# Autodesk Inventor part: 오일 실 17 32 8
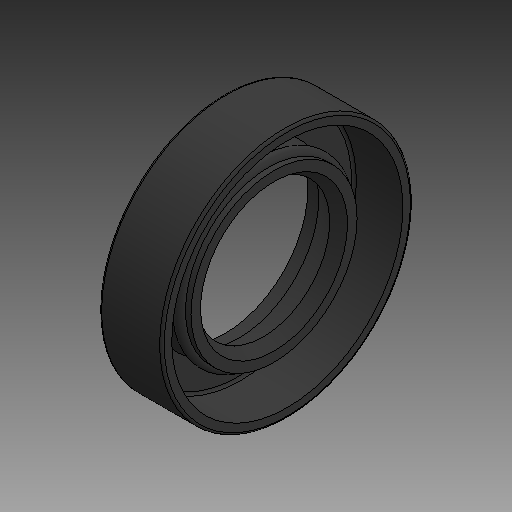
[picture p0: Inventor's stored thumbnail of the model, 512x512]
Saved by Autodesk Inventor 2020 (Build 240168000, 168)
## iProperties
Created: 2025-03
Part Number: 오일 실 17 32 8
Material: 고무
Description: 오일-실
Document SubType Name: Modeling
Designer: CA01
Density: 0.93 g/cm^3
Appearance: 기본값
Author: jhkim
Sending System: Autodesk Inventor 2025
Preprocessor: ST-DEVELOPER v20
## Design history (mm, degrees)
feature "Solid1"
node "솔리드1"
